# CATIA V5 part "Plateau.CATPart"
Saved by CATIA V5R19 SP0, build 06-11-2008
Part number: Plateau
Publications: "Li", "L", "Hg", "ep", "e"
Bounding box of the stored display mesh (mm): x -1000 to 0, y 0 to 820, z 0 to 70
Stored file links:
  G:\EU_thinkMotion\CFAO_2010\MMS_groupe3\MMS_groupe3\A reprendre\evulliez\evulliez\Plateau.CATPart
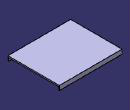
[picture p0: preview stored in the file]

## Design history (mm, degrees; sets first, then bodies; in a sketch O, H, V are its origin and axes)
Parameters
  Li = 800 mm
  L = 1000 mm
  Hg = 50 mm
  ep = 20 mm
  e = 10 mm
Body1 (main body)
  Sketch1 on yz-plane, origin (0, 0, 0), H (0, 1, 0), V (0, 0, 1)
    line L1 (0, 0) -> (10, 0)
    line L2 (0, 0) -> (0, 70)
    line L3 (10, 0) -> (10, 50)
    line L4 (10, 50) -> (810, 50)
    line L5 (810, 50) -> (810, 0)
    line L6 (810, 0) -> (820, 0)
    line L7 (820, 0) -> (820, 70)
    line L8 (0, 70) -> (820, 70)
    length L1 = 10 {= e}
    length L2 = 70 {= Hg +ep}
    length L3 = 50 {= Hg}
    length L4 = 800 {= Li}
    length L5 = 50 {= Hg}
    length L6 = 10 {= e}
    horizontal: L1 H, L4 H, L6 H, L8 H
    vertical: L2 V, L3 V, L5 V, L7 V
  Pad1: profile Sketch1, direction (-1, 0, 0), length 1000 {= L}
